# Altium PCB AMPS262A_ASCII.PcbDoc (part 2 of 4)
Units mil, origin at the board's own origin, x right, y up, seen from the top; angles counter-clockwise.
Board outline 5314.96 x 4803.15 mil, 4 copper layers (Top Layer, GND, Copper Layer 3, Bottom Layer), stack 79.28 mil thick; 324 components, 156 nets, 943 pads, 1411 vias.
Unrouted connection lines stored in the file: 130.
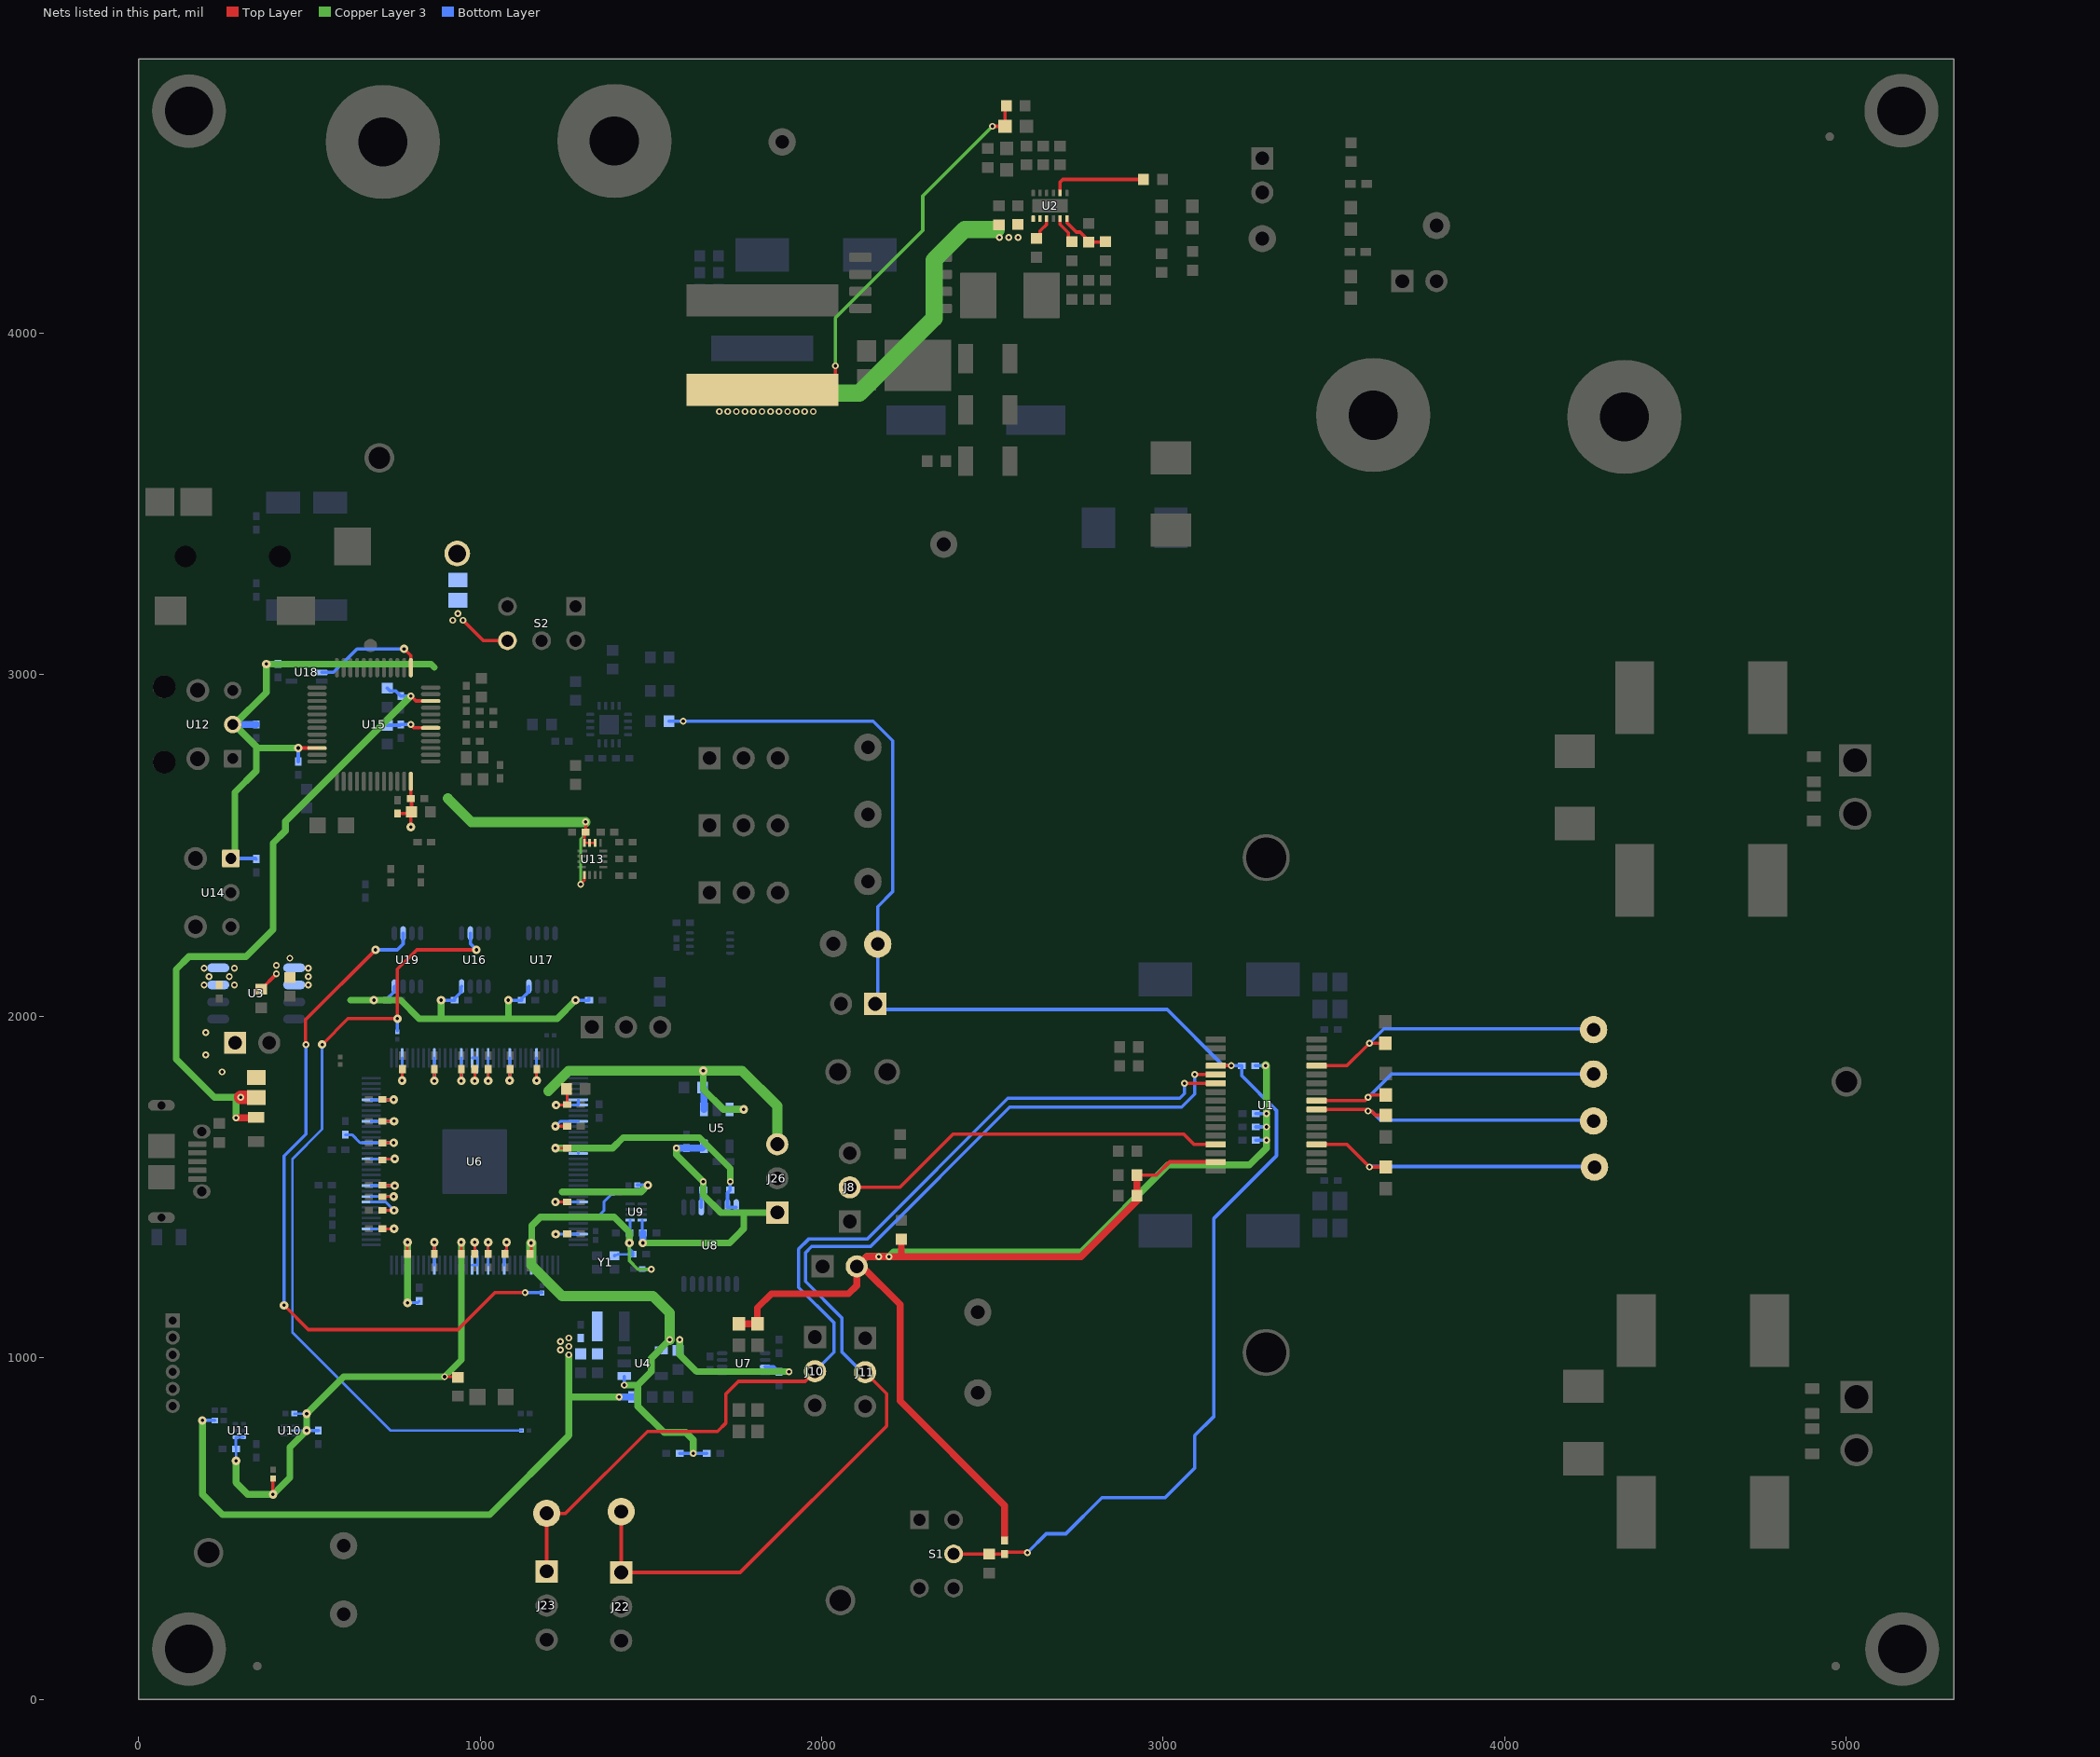
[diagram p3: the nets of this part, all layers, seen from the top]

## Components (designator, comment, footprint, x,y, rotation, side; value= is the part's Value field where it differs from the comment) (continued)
Y2 "ABM10-24.576MHZ-E20-T" XTAL_ABM10 984.25,2726.38 r180 top
ZZ1 "These assemblies are ESD sensitive, ESD precautions shall be observed." AssemblyNote 235,5703 r0 top
ZZ2 "These assemblies must be clean and free from flux and all contaminants. Use of no clean flux is not acceptable." AssemblyNote 235,5594.11 r0 top
ZZ3 "These assemblies must comply with workmanship standards IPC-A-610 Class 2, unless otherwise specified." AssemblyNote 235,5505.56 r0 top

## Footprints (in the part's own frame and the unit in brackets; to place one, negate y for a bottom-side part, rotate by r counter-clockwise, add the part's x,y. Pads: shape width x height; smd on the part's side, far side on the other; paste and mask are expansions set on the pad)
0201 [mm] "Data from Kemet datasheet CC101_COM dated 7/28/11"
  rect 0.46x0.42 smd mask+0: 1(-0.33,0) 2(0.33,0)
0201L [mm] "Data from Kemet datasheet CC101_COM dated 7/28/11"
  rect 0.36x0.32 smd mask+0: 1(-0.28,0) 2(0.28,0)
0402 [mm] "0402 from SM-752 data"
  rect 0.8x0.6 smd: 1(-0.6,0) 2(0.6,0)
  silkscreen extent -1.22,-0.52 1.22,0.52
0402L [mm] "0402 from SM-752 data"
  rect 0.6x0.5 smd: 1(-0.5,0) 2(0.5,0)
0603 [mm] "0603 from SM-752 data"
  rect 1x0.95 smd: 1(-0.8,0) 2(0.8,0)
  silkscreen extent -1.52,-0.69 1.52,0.69
0603L [mm] "0603 from SM-752 data"
  rect 0.8x0.85 smd: 1(-0.7,0) 2(0.7,0)
  silkscreen extent -0.07,-0.33 0.07,0.33
0805L [mm] "0805 from SM-752 data"
  rect 1.1x1.4 smd: 1(-0.75,0) 2(0.75,0)
1008 [mm] "SMD, Body 2.5x2mm, Height 1.2mm"
  rect 0.8x2.2 smd: 1(-1,0) 2(1,0)
  silkscreen extent -0.4,-1.2 0.4,1.2
1210_280 [mm] "SMD, 2-Leads, Body 3.6x2.8mm, Height 2.8mm"
  rect 1.1x2.2 smd: 1(-1.65,0) 2(1.65,0)
  silkscreen extent -0.84,-1.4 0.84,1.4
2512_WIDE_VISHAY [mm] "Vishay recommended land pattern"
  rect 1.9x7.6 smd: 1(-1.55,0) 2(1.55,0)
  silkscreen extent -0.3,-3.32 0.3,3.35
"APM_RM3X8MM 2701" [mm] "Screw, Dia 6.7mm, Length 8mm, TH"
  round 5.5 hole 3.6: ""(0,0)
  silkscreen extent -3.35,-3.35 3.35,3.35
AssemblyNote [mil] "Assembly Note"
CE_Mark_5mm [mil] "Minimum text height for CE Mark"
CONN_1040 [mil] "Test Point, PC  test point Terminal"
  round 75 hole 52: 1(0,0)
D0008A_M [mm] "SOIC, 8-Leads, Body 4.9x3.9mm, Pitch 1.27mm, IPC Low Density"
  oval 1.65x0.65 smd: 1(-2.825,1.905) 2(-2.825,0.635) 3(-2.825,-0.635) 4(-2.825,-1.905) 5(2.825,-1.905) 6(2.825,-0.635) 7(2.825,0.635) 8(2.825,1.905)
  silkscreen extent -3.3,-2.5 0.9,2.5
DAD0032A-MFG [mm] "Recommended Land Pattern"
  rrect22% 1.5x0.45 smd paste+0 mask+0: 1(-3.75,4.875) 2(-3.75,4.225) 3(-3.75,3.575) 4(-3.75,2.925) 5(-3.75,2.275) 6(-3.75,1.625) 7(-3.75,0.975) 8(-3.75,0.325) 9(-3.75,-0.325) 10(-3.75,-0.975) 11(-3.75,-1.625) 12(-3.75,-2.275) 13(-3.75,-2.925) 14(-3.75,-3.575) 15(-3.75,-4.225) 16(-3.75,-4.875) 17(3.75,-4.875) 18(3.75,-4.225) 19(3.75,-3.575) 20(3.75,-2.925) 21(3.75,-2.275) 22(3.75,-1.625) 23(3.75,-0.975) 24(3.75,-0.325) 25(3.75,0.325) 26(3.75,0.975) 27(3.75,1.625) 28(3.75,2.275) 29(3.75,2.925) 30(3.75,3.575) 31(3.75,4.225) 32(3.75,4.875)
  silkscreen extent -5.17,-5.55 3.1,5.55
DBV0005A_N [mm] "SOT23, 5-Leads, Body 2.9x1.6mm, Pitch 0.95mm, Lead Span 2.8mm, IPC Medium Density"
  rrect17% 1x0.6 smd: 1(-1.375,0.95) 2(-1.375,0) 3(-1.375,-0.95) 4(1.375,-0.95) 5(1.375,0.95)
  silkscreen extent -0.25,-1.55 0.25,1.55
DCK0005A_N [mm] "SOT353, 5-Leads, Body 2x1.3mm, Pitch 0.65mm, Lead Span 2.1mm, IPC Medium Density"
  rrect25% 0.85x0.4 smd: 1(-1.125,0.65) 2(-1.125,0) 3(-1.125,-0.65) 4(1.125,-0.65) 5(1.125,0.65)
  silkscreen extent -1.48,-1.02 0.55,1.1
DCT0008A_N [mm] "TSOP, 8-Leads, Body 3x2.8mm, Pitch 0.65mm, IPC Medium Density"
  oval 1.05x0.4 smd: 1(-1.975,0.975) 2(-1.975,0.325) 3(-1.975,-0.325) 4(-1.975,-0.975) 5(1.975,-0.975) 6(1.975,-0.325) 7(1.975,0.325) 8(1.975,0.975)
  silkscreen extent -2.32,-1.57 0.6,1.58
DCU0008A_L [mm] "TSSOP, 8-Leads, Body 2x2.3mm, Pitch 0.5mm, IPC High Density"
  oval 0.6x0.25 smd: 1(-1.5,0.75) 2(-1.5,0.25) 3(-1.5,-0.25) 4(-1.5,-0.75) 5(1.5,-0.75) 6(1.5,-0.25) 7(1.5,0.25) 8(1.5,0.75)
  silkscreen extent -1.05,-1.05 0.38,1.05
DCU0008A_N [mm] "TSSOP, 8-Leads, Body 2x2.3mm, Pitch 0.5mm, IPC Medium Density"
  oval 0.8x0.3 smd: 1(-1.6,0.75) 2(-1.6,0.25) 3(-1.6,-0.25) 4(-1.6,-0.75) 5(1.6,-0.75) 6(1.6,-0.25) 7(1.6,0.25) 8(1.6,0.75)
  silkscreen extent -1.05,-1.05 0.38,1.05
DQM0008A [mm] "TI"
  rrect50% 0.7x0.2 smd: 1(-0.45,0.6) 2(-0.45,0.2) 3(-0.45,-0.2) 4(-0.45,-0.6) 5(0.45,-0.6) 6(0.45,-0.2) 7(0.45,0.2) 8(0.45,0.6)
  silkscreen extent -0.72,-1.02 0.72,1.02
DRY0006A [mm] "USON-6"
  rrect67% 0.45x0.3 smd paste-0.05 mask+0: 1(-0.275,0.5)
  rrect67% 0.4x0.3 smd paste-0.05 mask+0: 2(-0.3,0) 3(-0.3,-0.5) 4(0.3,-0.5) 5(0.3,0) 6(0.3,0.5)
DSF0006A [mm] "TI recommended land pattern"
  rrect59% 0.6x0.17 smd mask+0: 1(-0.4,0.35) 2(-0.4,0) 3(-0.4,-0.35) 4(0.4,-0.35) 5(0.4,0) 6(0.4,0.35)
  silkscreen extent -0.6,-0.63 0.6,0.63
DSS0012B [mm] "WSON-10"
  rrect40% 0.5x0.25 smd: 1(-0.95,1.25) 2(-0.95,0.75) 3(-0.95,0.25) 4(-0.95,-0.25) 5(-0.95,-0.75) 6(-0.95,-1.25) 7(0.95,-1.25) 8(0.95,-0.75) 9(0.95,-0.25) 10(0.95,0.25) 11(0.95,0.75) 12(0.95,1.25)
  rrect11% 1x2.65 smd paste-0.5: 13(0,0)
ERJMS4S [mm] "SMD, 2-Leads, Body 6.4x3.2mm"
  rrect4% 2.7x3.4 smd: 1(-2.35,0) 2(2.35,0)
  silkscreen extent -0.7,-1.55 0.7,1.55
FCC_disclaimer_stacked [mil]
Fiducial6.4-20 [mil]
  round 25 smd mask+0: 1(0,0)
  Top Layer keep-out circle w46.37: c0,0 r19.68
FP-ASA-24.000MHZ-L-T_SMD_2MM0_1MM6-MFG [mm]
  rrect15% 0.75x0.65 smd paste+0 mask+0: 1(-0.65,-0.5) 2(0.65,-0.5) 3(0.65,0.5) 4(-0.65,0.5)
  silkscreen extent -1.45,-1.52 1.45,0.85
FP-CGA4J3X7R1H684M125AB_0805-MFG [mm]
  rrect13% 0.8x1.05 smd paste+0 mask+0: 1(-0.925,0) 2(0.925,0)
FP-FCR684208T_OTJ8-MFG [mm]
  rrect8% 1.3x1.3 hole 0.8 paste-1000 mask+0: 1(-4.25,2.54)
  round 1.3 hole 0.8 paste-1000 mask+0: 2(-4.25,0) 3(-4.25,-2.54)
  round 1.7 hole 1.1 paste-1000 mask+0: 4(-1.65,2.54) 5(-1.65,-2.54)
  round 1.7 hole 1.7 unplated paste-1000 mask+0: ""(0.85,2.8) ""(0.85,-2.8)
  silkscreen extent -7.45,-4.95 6.85,4.95
FP-PLR237/T10BK_PTH_9MM70_13MM50-MFG [mm] "EVERLIGHT"
  rrect8% 1.3x1.3 hole 0.8 paste-1000 mask+0: 1(-2.54,4.36)
  round 1.3 hole 0.8 paste-1000 mask+0: 2(0,4.36) 3(2.54,4.36)
  round 1.7 hole 1.1 paste-1000 mask+0: 4(-2.54,1.74) 5(2.54,1.74)
  silkscreen extent -5.6,-6.9 5,6.9
HARWIN_S1911-46R [mm] "HARWIN"
  rect 2.48x3 smd mask+0: 1(-2.69,0) 2(2.69,0)
  silkscreen extent -0.5,-1.5 0.5,1.5
HSINK_ATS078036036-TI1OP-519-C1-R3 [mm] "TH, 2-Leads, Body 78x36mm, Height 35.6mm"
  round 3.5 hole 3: 1(-18.4,0) 2(18.4,0)
HXB_JA0 [mm] "SMD, 2-Leads, Dia 10mm"
  rect 4.4x2.2 smd: 1(-4.45,0) 2(4.45,0)
  silkscreen extent -5.25,-5.25 5.25,5.25
JST_B2PS-VH [mm] "JST Sales America Inc"
  rect 2.4x2.4 hole 1.778: 1(0,1.98)
  round 2.4 hole 1.778: 2(0,-1.98)
  silkscreen extent 2,-3.93 14.9,3.93
Keystone5003 [mil] "For Keystone 500x miniature loop terminals"
  round 80 hole 40: 1(0,0)
  silkscreen extent -52,-52 52,52
Keystone5006 [mil] "Keystone Compact loops"
  round 87 hole 63: 1(0,0)
  silkscreen extent -70,-70 70,70
Keystone_7006 [mm] "KEYSTONE"
  round 8.5 hole 3.658: 1(0,0)
  silkscreen extent -4.8,-4.8 4.8,4.8
Keystone_7007 [mm] "KEYSTONE"
  round 8.5 hole 3.658: 1(0,0)
  silkscreen extent -4.8,-4.8 4.8,4.8
Keystone_24434 [mil] "Keystone"
LTST-C170TBKT_Blue [mm] "LITE-ON"
  rect 1.2x1.2 smd: 1(-1.05,0) 2(1.05,0)
  silkscreen extent -1.6,-1 2.2,1
Molex_0475890001 [mm] "Molex"
  rrect25% 0.4x1.35 smd: 1(-1.3,4.125) 2(-0.65,4.125) 3(0,4.125) 4(0.65,4.125) 5(1.3,4.125)
  oval 1.05x1.3 hole 0.7 slot 0.85 at 90 deg: 6(2.225,4.45) 11(-2.225,4.45)
  oval 0.8x2 hole 0.6 slot 1.3 at 90 deg: 7(4.175,1.45) 10(-4.175,1.45)
  rrect6% 1.8x2 smd: 8(1.15,1.45) 9(-1.15,1.45)
  silkscreen extent -3.75,2.85 3.75,4.3
MPZ2012 [mm] "TDK"
  rect 0.8x1.2 smd: 1(-0.9,0) 2(0.9,0)
PBC03SAAN [mm] "Sullins 100mil, 1x3, 230 mil above insulator"
  rect 1.65x1.65 hole 1.016: 1(-2.54,0)
  round 1.65 hole 1.016: 2(0,0) 3(2.54,0)
  silkscreen extent -3.81,-1.27 3.81,1.27
PG-TDSON-8-33 [mm] "Infineon recommended land pattern"
  rrect29% 1.65x0.7 smd paste-1 mask+0: 1(-2.995,1.905) 2(-2.995,0.635) 3(-2.995,-0.635) 4(-2.995,-1.905) 5(2.995,-1.905) 6(2.995,-0.635) 7(2.995,0.635) 8(2.995,1.905)
PT0048A_N [mm] "Thin QFP, 48-Leads, Body 7x7mm, Pitch 0.5mm, IPC Medium Density"
  oval 1.45x0.3 smd: 1(-4.225,2.75) 2(-4.225,2.25) 3(-4.225,1.75) 4(-4.225,1.25) 5(-4.225,0.75) 6(-4.225,0.25) 7(-4.225,-0.25) 8(-4.225,-0.75) 9(-4.225,-1.25) 10(-4.225,-1.75) 11(-4.225,-2.25) 12(-4.225,-2.75) 25(4.225,-2.75) 26(4.225,-2.25) 27(4.225,-1.75) 28(4.225,-1.25) 29(4.225,-0.75) 30(4.225,-0.25) 31(4.225,0.25) 32(4.225,0.75) 33(4.225,1.25) 34(4.225,1.75) 35(4.225,2.25) 36(4.225,2.75)
  oval 0.3x1.45 smd: 13(-2.75,-4.225) 14(-2.25,-4.225) 15(-1.75,-4.225) 16(-1.25,-4.225) 17(-0.75,-4.225) 18(-0.25,-4.225) 19(0.25,-4.225) 20(0.75,-4.225) 21(1.25,-4.225) 22(1.75,-4.225) 23(2.25,-4.225) 24(2.75,-4.225) 37(2.75,4.225) 38(2.25,4.225) 39(1.75,4.225) 40(1.25,4.225) 41(0.75,4.225) 42(0.25,4.225) 43(-0.25,4.225) 44(-0.75,4.225) 45(-1.25,4.225) 46(-1.75,4.225) 47(-2.25,4.225) 48(-2.75,4.225)
  silkscreen extent -4.35,-3.1 3.1,3.58
PW0014A_L [mm] "TSOP, 14-Leads, Body 5x4.4mm, Pitch 0.65mm, IPC High Density"
  oval 1.2x0.4 smd: 1(-2.85,1.95) 2(-2.85,1.3) 3(-2.85,0.65) 4(-2.85,0) 5(-2.85,-0.65) 6(-2.85,-1.3) 7(-2.85,-1.95) 8(2.85,-1.95) 9(2.85,-1.3) 10(2.85,-0.65) 11(2.85,0) 12(2.85,0.65) 13(2.85,1.3) 14(2.85,1.95)
  silkscreen extent -3.2,-2.55 1.85,2.55
RGT0016A [mm] "QFN, 16-Leads, Body 3x3mm, Pitch 0.5mm, Thermal Pad 1.45x1.45mm, TI Recommended"
  rrect42% 0.6x0.24 smd: 1(-1.4,0.75) 2(-1.4,0.25) 3(-1.4,-0.25) 4(-1.4,-0.75) 9(1.4,-0.75) 10(1.4,-0.25) 11(1.4,0.25) 12(1.4,0.75)
  rrect42% 0.24x0.6 smd: 5(-0.75,-1.4) 6(-0.25,-1.4) 7(0.25,-1.4) 8(0.75,-1.4) 13(0.75,1.4) 14(0.25,1.4) 15(-0.25,1.4) 16(-0.75,1.4)
  rrect7% 1.34x1.34 on Bottom Paste: 17(0,0)
  rrect7% 1.45x1.45 smd paste-0.725: 17(0,0)
  silkscreen extent -1.72,-1.73 1.72,1.73
RSV0016A [mm] "QFN, 16-Leads, Body 1.8x2.6mm, Pitch 0.4mm, TI Recommended"
  rect 0.7x0.2 smd: 1(-0.75,0.6)
  rect 0.6x0.2 smd: 2(-0.8,0.2) 3(-0.8,-0.2) 4(-0.8,-0.6) 9(0.8,-0.6) 10(0.8,-0.2) 11(0.8,0.2) 12(0.8,0.6)
  rect 0.2x0.6 smd: 5(-0.6,-1.2) 6(-0.2,-1.2) 7(0.2,-1.2) 8(0.6,-1.2) 13(0.6,1.2) 14(0.2,1.2) 15(-0.2,1.2) 16(-0.6,1.2)
  silkscreen extent -1.08,-1.33 1.08,1.45
SM_RADIAL_10BMM [mm] "Nichicon 10x10"
  rect 4x2.5 smd: 1(-4,0) 2(4,0)
  silkscreen extent -5.25,-5.25 5.25,5.25
SM_RADIAL_B [mm] "4 x 5.8mm:  Panasonic B"
  rect 2.5x1.6 smd: 1(-1.75,0) 2(1.75,0)
  silkscreen extent -2.24,-2.25 2.25,2.25
SNT-100-BK-G [mil] "Samtec STEP model"
  round 1 on Mech3: 0(0,0)
SOT1289 [mm] "CFP15, Nexperia recommended land pattern"
  rect 1.6x1.44 smd paste-0.8 mask+0: 1(-1.065,2.78) 2(1.065,2.78)
  rect 3.8x4.96 smd paste-2.48 mask+0: 3(0,-1.02)
SULLINS_LPPB061NGCN-RC [mm] "SULLINS"
  rect 1.05x1.05 hole 0.61: 1(3.175,2.54)
  round 1.05 hole 0.61: 2(1.905,2.54) 3(0.635,2.54) 4(-0.635,2.54) 5(-1.905,2.54) 6(-3.175,2.54)
  silkscreen extent -4,-2.37 4.03,2
Sullins_PBC02SAAN [mm] "Sullins 100mil, 1x2, 230 mil above insulator"
  rect 1.65x1.65 hole 1.016: 1(0,1.27)
  round 1.65 hole 1.016: 2(0,-1.27)
  silkscreen extent -1.37,-2.54 1.27,3.1
SW_200USP1T1A1M2 [mm] "TH, 5-Leads, Body 7x4.5mm, Pitch 2.54mm"
  rect 1.4x1.4 hole 0.9: 1(-1.27,2.54)
  round 1.4 hole 0.9: 3(-1.27,-2.54) 4(1.27,2.54) 5(1.27,0) 6(1.27,-2.54)
  silkscreen extent -2.7,-3.63 2.38,3.63
Switchcraft_35RASM [mil] "Switchcraft"
  rect 83x92 smd: 1(-159.5,142.5) 2(159.5,67.5)
  rect 83x111 smd: 3(-159.5,-224.5)
  rect 83x84 smd: 4(159.5,173.5)
  rect 111x107 smd: 5(29,-390.5)
  rect 0x0 hole 63 unplated: MH1(0,98.5) MH2(0,-177.5)
  silkscreen extent -161,-339 121,340
TI_Stacked_Overlay_Small [mil]
TP_SM_1MM [mm] "1mm Test Point, SMT"
  round 1 smd paste-0.5: 1(0,0)
TQFP-128 [mm] "TQFP, 128-Leads, Body 14x14mm, Pitch 0.4mm"
  rrect50% 1.45x0.2 smd: 1(-7.7,6.2) 2(-7.7,5.8) 3(-7.7,5.4) 4(-7.7,5) 5(-7.7,4.6) 6(-7.7,4.2) 7(-7.7,3.8) 8(-7.7,3.4) 9(-7.7,3) 10(-7.7,2.6) 11(-7.7,2.2) 12(-7.7,1.8) 13(-7.7,1.4) 14(-7.7,1) 15(-7.7,0.6) 16(-7.7,0.2) 17(-7.7,-0.2) 18(-7.7,-0.6) 19(-7.7,-1) 20(-7.7,-1.4) 21(-7.7,-1.8) 22(-7.7,-2.2) 23(-7.7,-2.6) 24(-7.7,-3) 25(-7.7,-3.4) 26(-7.7,-3.8) 27(-7.7,-4.2) 28(-7.7,-4.6) 29(-7.7,-5) 30(-7.7,-5.4) 31(-7.7,-5.8) 32(-7.7,-6.2) 65(7.7,-6.2) 66(7.7,-5.8) 67(7.7,-5.4) 68(7.7,-5) 69(7.7,-4.6) 70(7.7,-4.2) 71(7.7,-3.8) 72(7.7,-3.4) 73(7.7,-3) 74(7.7,-2.6) 75(7.7,-2.2) 76(7.7,-1.8) 77(7.7,-1.4) 78(7.7,-1) 79(7.7,-0.6) 80(7.7,-0.2) 81(7.7,0.2) 82(7.7,0.6) 83(7.7,1) 84(7.7,1.4) 85(7.7,1.8) 86(7.7,2.2) 87(7.7,2.6) 88(7.7,3) 89(7.7,3.4) 90(7.7,3.8) 91(7.7,4.2) 92(7.7,4.6) 93(7.7,5) 94(7.7,5.4) 95(7.7,5.8) 96(7.7,6.2)
  rrect50% 0.2x1.45 smd: 33(-6.2,-7.7) 34(-5.8,-7.7) 35(-5.4,-7.7) 36(-5,-7.7) 37(-4.6,-7.7) 38(-4.2,-7.7) 39(-3.8,-7.7) 40(-3.4,-7.7) 41(-3,-7.7) 42(-2.6,-7.7) 43(-2.2,-7.7) 44(-1.8,-7.7) 45(-1.4,-7.7) 46(-1,-7.7) 47(-0.6,-7.7) 48(-0.2,-7.7) 49(0.2,-7.7) 50(0.6,-7.7) 51(1,-7.7) 52(1.4,-7.7) 53(1.8,-7.7) 54(2.2,-7.7) 55(2.6,-7.7) 56(3,-7.7) 57(3.4,-7.7) 58(3.8,-7.7) 59(4.2,-7.7) 60(4.6,-7.7) 61(5,-7.7) 62(5.4,-7.7) 63(5.8,-7.7) 64(6.2,-7.7) 97(6.2,7.7) 98(5.8,7.7) 99(5.4,7.7) 100(5,7.7) 101(4.6,7.7) 102(4.2,7.7) 103(3.8,7.7) 104(3.4,7.7) 105(3,7.7) 106(2.6,7.7) 107(2.2,7.7) 108(1.8,7.7) 109(1.4,7.7) 110(1,7.7) 111(0.6,7.7) 112(0.2,7.7) 113(-0.2,7.7) 114(-0.6,7.7) 115(-1,7.7) 116(-1.4,7.7) 117(-1.8,7.7) 118(-2.2,7.7) 119(-2.6,7.7) 120(-3,7.7) 121(-3.4,7.7) 122(-3.8,7.7) 123(-4.2,7.7) 124(-4.6,7.7) 125(-5,7.7) 126(-5.4,7.7) 127(-5.8,7.7) 128(-6.2,7.7)
  rrect2% 4.8x4.8 smd paste-4.8: 129(0,0)
  silkscreen extent -7.1,-7.1 7.1,7.1
WE-PD_1210 [mm] "Wurth Elektronik recommended land pattern"
  rect 2.9x5.4 smd: 1(-4.95,0) 2(4.95,0)
  silkscreen extent -6,-6 6,6
WEEE_Minimum [mil] "WEEElie bin"
  silkscreen extent 22,-71 54,74
XAL1010 [mm] "COILCRAFT"
  rect 2.38x11.31 smd: 1(-3.325,0) 2(3.325,0)
  silkscreen extent -5.3,-6 5.3,6
XTAL_ABM10 [mm] "ABRACON"
  rect 0.8x0.9 smd: 1(-0.625,0.825) 2(-0.625,-0.825) 3(0.625,-0.825) 4(0.625,0.825)
  silkscreen extent -1.28,-0.13 1.05,1.52

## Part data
C1 C10 C13 C21: library part CMP-0086459-1, "CAP CER 0.68UF 50V X7R 0805"
C2 C3 C6 C7: library part CMP-0007842-2, "CAP, CERM, 10 uF, 35 V, +/- 10%, X5R, 0805"
C4 C5: library part CMP-0006325-2, "CAP, CERM, 0.1 uF, 50 V, +/- 10%, X7R, AEC-Q200 Grade 1, 0402"
C8 C9: library part CMP-0011092-1, "CAP, AL, 390 uF, 35 V, +/- 20%, 0.08 ohm, SMD"
C11: library part CMP-0006949-5, "CAP, CERM, 4.7 uF, 10 V, +/- 10%, X5R, 0603"
C12 C22: library part CMP-0006860-5, "CAP, CERM, 0.1 uF, 16 V, +/- 10%, X7R, 0603"
C14 C16 C18 C20: library part CMP-0007050-4, "CAP, CERM, 0.47 uF, 50 V, +/- 10%, X7R, 0603"
C15 C17 C19: library part CMP-0082012-1, "CAP, CERM, 1 µF, 16 V,+/- 20%, X7R, 0603"
C23: library part CMP-0012596-3, "CAP, Polymer Hybrid, 100 uF, 50 V, +/- 20%, 28 ohm, 10x10 SMD"
C24 C25 C26: library part CMP-0860569-1, "CAP, CERM, 10 µF, 25 V,+/- 10%, X5R, 0603"
C27: library part CMP-0080610-1, "CAP, CERM, 0.1 µF, 25 V,+/- 10%, X7R, AEC-Q200 Grade 1, 0402"
C28: library part CMP-0007078-4, "CAP, CERM, 0.1 uF, 50 V, +/- 10%, X7R, AEC-Q200 Grade 1, 0603"
C29 C30 C31: library part CMP-0009162-2, "CAP, CERM, 4.7 uF, 50 V, +/- 10%, X7R, AEC-Q200 Grade 1, 1210"
C32: library part CMP-0012269-3, "CAP, Aluminum Polymer, 100 uF, 50 V, +/- 20%, 0.025 ohm, AEC-Q200 Grade 2, D10xL10mm SMD"
C33: library part CMP-0007137-5, "CAP, CERM, 1 uF, 16 V, +/- 20%, X7R, AEC-Q200 Grade 1, 0603"
C34: library part CMP-0007143-4, "CAP, CERM, 0.01 uF, 50 V, +/- 10%, X7R, AEC-Q200 Grade 1, 0603"
C35 C36: library part CMP-0080091-1, "CAP, CERM, 100 pF, 50 V,+/- 1%, C0G/NP0, 0603"
C37: library part CMP-0007094-5, "CAP, CERM, 0.22 uF, 50 V, +/- 10%, X7R, AEC-Q200 Grade 1, 0603"
C38: library part CMP-0007072-4, "CAP, CERM, 220 pF, 20 V, +/- 5%, C0G/NP0, AEC-Q200 Grade 1, 0603"
C39: library part CMP-0006900-4, "CAP, CERM, 0.022 uF, 16 V, +/- 10%, X7R, 0603"
C40 C41: library part CMP-0079606-1, "CAP, CERM, 220 pF, 50 V,+/- 5%, C0G/NP0, AEC-Q200 Grade 1, 0402"
C42 C44 C45 C46 C47 C48 C49 C50 C51 C52 C53 C54 C55 C56 C57 C61 C65 C66 C67 C68 C69 C70 C71 C72 C73 C74 C75 C76 C77 C78 C79 C80 C81 C82 C83 C85 C86 C88 C89 C90 C91 C92 C93 C94 C95 C97 C99 C100 C104 C111 C114 C115 C116 C117 C118 C119 C120: library part CMP-0006228-2, "CAP, CERM, 0.1 uF, 16 V, +/- 10%, X7R, 0402"
C43 C62: library part CMP-0007003-5, "CAP, CERM, 10 uF, 10 V, +/- 20%, X5R, 0603"
C58 C59 C60: library part CMP-0007005-5, "CAP, CERM, 22 uF, 10 V, +/- 20%, X5R, 0603"
C63: library part CMP-0006372-2, "CAP, CERM, 1 uF, 6.3 V, +/- 20%, X5R, 0402"
C64: library part CMP-0006227-2, "CAP, CERM, 0.01 uF, 16 V, +/- 10%, X7R, 0402"
C84: library part CMP-0006470-2, "CAP, CERM, 470 pF, 50 V, +/- 5%, C0G/NP0, 0402"
C87: library part CMP-0007370-4, "CAP, CERM, 2.2 uF, 10 V, +/- 10%, X7R, 0603"
C96 C98 C101 C110: library part CMP-0007122-5, "CAP, CERM, 10 uF, 16 V, +/- 20%, X5R, 0603"
C102 C103 C107: library part CMP-0006215-2, "CAP, CERM, 10 pF, 50 V, +/- 5%, C0G/NP0, 0402"
C105 C106: library part CMP-0006365-2, "CAP, CERM, 27 pF, 50 V, +/- 5%, C0G/NP0, 0402"
C108 C109: library part CMP-0010644-1, "CAP, AL, 10 uF, 16 V, +/- 20%, 3 ohm, SMD"
C112: library part CMP-0860557-1, "CAP, CERM, 4700 pF, 25 V,+/- 10%, X7R, 0402"
C113: library part CMP-0006331-2, "CAP, CERM, 0.068 uF, 50 V, +/- 10%, X7R, AEC-Q200 Grade 1, 0402"
D1: library part CMP-0028984-3, "Diode, Schottky, 60 V, 10 A, AEC-Q101, CFP15"
D2 D3: library part CMP-0002889-2, "LED, Blue, SMD"
FID1 FID2 FID3 FID4 FID5 FID6: library part CMP-0077181-1, "Fiducial mark.  There is nothing to buy or mount."
H1: library part CMP-0004031-2, "Heat Sink, Vertical"
H2 H3 H4 H5: library part CMP-0003717-1, "MACHINE SCREW PAN PHILLIPS M3"
H6 H7 H8 H9: library part CMP-0003665-1, "Standoff, Hex, 12mm, M3, Aluminum"
J1 J7 J14 J18: library part CMP-0075020-1, "JUMPER TIN SMD"
J2 J6: library part CMP-0074989-1, "Header (friction lock), 3.96mm, 2x1, Tin, R/A, TH"
J3 J9 J15 J16 J19: library part CMP-0054566-1, "Header, 100mil, 2x1, Gold, TH"
J4 J5 J21: library part CMP-0055161-1
J8 J10 J11 J22 J23 J26 J27 J28 J29 J31: library part CMP-0002334-1, "Header, 100mil, 3x1, Gold, TH"
J12 J17: library part CMP-0055127-1, "Binding Post, RED, TH"
J13 J20: library part CMP-0055128-1, "Binding Post, BLACK, TH"
J24: library part CMP-0054640-1, "Receptacle, 50mil, 6x1, Gold, R/A, TH"
J25: library part CMP-0055301-1, "Connector, Receptacle, Micro-USB Type AB, R/A, Bottom Mount SMT"
J30: library part CMP-0074987-1, "Audio Jack, 3.5mm, Stereo, R/A, SMT"
L1 L2 L3 L4: library part CMP-0064206-1, "Inductor, Shielded Drum Core, Ferrite, 10 uH, 7.1 A, 0.01294 ohm, SMD"
L5: library part CMP-0060953-1, "Inductor, Shielded, Composite, 6.8 uH, 18.5 A, 0.01 ohm, SMD"
L6: library part CMP-0058752-1, "Inductor, Multilayer, Ferrite, 2.2 uH, 1.3 A, 0.08 ohm, SMD"
L7 L8: library part CMP-0003429-3, "Ferrite Bead, 600 ohm @ 100 MHz, 2 A, 0805"
Logo1: library part CMP-0074844-2
Logo2: library part CMP-0074838-1, "Texas Instrument Corporate Signature"
Logo3: library part CMP-0074847-1, "FCC_disclaimer"
Logo4: library part CMP-0074769-4
Q1: library part CMP-0080659-3, "MOSFET, N-CH, 40 V, 50 A, AEC-Q101, SON-8"
R1 R6 R15 R17 R22 R25 R26 R30 R73 R74 R75 R76 R77 R78 R80: library part CMP-0025885-5, "RES, 0, 5%, 0.1 W, 0603"
R2: library part CMP-0065359-1, "RES, 15.0 k, .1%, .063 W, AEC-Q200 Grade 0, 0402"
R3 R36: library part CMP-0026852-3, "RES, 1.0 k, 5%, 0.063 W, AEC-Q200 Grade 0, 0402"
R4 R5 R7 R66 R79: library part CMP-0025958-3, "RES, 10.0 k, 1%, 0.063 W, AEC-Q200 Grade 0, 0402"
R8 R9: library part CMP-0025906-5, "RES, 2.2 k, 5%, 0.1 W, 0603"
R10 R11: library part CMP-0025899-5, "RES, 1.0 k, 5%, 0.1 W, 0603"
R12: library part CMP-0015368-2, "RES, 0, 5%, 2 W, 2512 WIDE"
R13 R19: library part CMP-0022914-5, "RES, 21.0 k, 1%, 0.1 W, 0603"
R14 R64: library part CMP-0023343-3, "RES, 0, 1%, 0.1 W, AEC-Q200 Grade 0, 0603"
R16: library part CMP-0022944-5, "RES, 24.9 k, 1%, 0.1 W, 0603"
R18: library part CMP-0022736-4, "RES, 100, 1%, 0.1 W, 0603"
R20: library part CMP-0022447-4, "RES, 49.9 k, 1%, 0.1 W, AEC-Q200 Grade 0, 0603"
R21: library part CMP-0015077-2, "RES, 0.004, 1%, 3 W, AEC-Q200 Grade 0, 6.4x3.2mm"
R23: library part CMP-0023239-5, "RES, 68.0 k, 1%, 0.1 W, 0603"
R24: library part CMP-0022017-4, "RES, 11.3 k, 1%, 0.1 W, AEC-Q200 Grade 0, 0603"
R27 R28: library part CMP-0022684-3, "RES, 10.0 k, 1%, 0.1 W, 0603"
R29: library part CMP-0023148-5, "RES, 4.30 k, 1%, 0.1 W, 0603"
R31 R33: library part CMP-0020803-2, "RES, 0, 5%, 0.125 W, 0805"
R32: library part CMP-0022941-4, "RES, 249 k, 1%, 0.1 W, 0603"
R34: library part CMP-0023232-5, "RES, 66.5 k, 1%, 0.1 W, 0603"
R35: library part CMP-0022735-5, "RES, 100 k, 1%, 0.1 W, 0603"
R37 R38: library part CMP-0026890-5, "RES, 2.2 k, 5%, 0.063 W, AEC-Q200 Grade 0, 0402"
R39 R46: library part CMP-0026658-1, "RES, 10.0 k, 1%, 0.1 W, 0402"
R40: library part CMP-0025821-4, "RES, 4.7, 5%, 0.1 W, AEC-Q200 Grade 0, 0603"
R41: library part CMP-0026825-5, "RES, 10 k, 5%, 0.063 W, AEC-Q200 Grade 0, 0402"
R42 R43 R44 R47 R52 R53 R56: library part CMP-0027614-1, "RES, 33.2, 1%, 0.05 W, 0201"
R45: library part CMP-0023235-5, "RES, 680, 1%, 0.1 W, 0603"
R48: library part CMP-0065361-1, "RES, 0, 5%, .05 W, AEC-Q200 Grade 0, 0201"
R49: library part CMP-0082538-1, "RES, 43.2, 1%, 0.1 W, AEC-Q200 Grade 0, 0402"
R50 R51 R55 R57 R72: library part CMP-0027262-3, "RES, 10.0 k, 1%, 0.05 W, 0201"
R54: library part CMP-0027523-1, "RES, 25.5 k, 1%, 0.05 W, 0201"
R58: library part CMP-0027757-1, "RES, 51.0 k, 1%, 0.05 W, 0201"
R59: library part CMP-0026737-1, "RES, 47.0 k, 1%, 0.0625 W, 0402"
R60 R65 R67: library part CMP-0026404-2, "RES, 49.9, 1%, 0.063 W, AEC-Q200 Grade 0, 0402"
R61 R62 R63: library part CMP-0026696-1, "RES, 33.0, 1%, 0.1 W, 0402"
R68: library part CMP-0025733-4, "RES, 1.5 k, 5%, 0.1 W, AEC-Q200 Grade 0, 0603"
R69 R70: library part CMP-0026873-2, "RES, 200 k, 5%, 0.063 W, AEC-Q200 Grade 0, 0402"
R71: library part CMP-0026962-3, "RES, 680, 5%, 0.063 W, AEC-Q200 Grade 0, 0402"
S1 S2: library part CMP-0002209-2, "Switch, SPDT, On-On, 2 Pos, TH"
SH-J1 SH-J2 SH-J3 SH-J4 SH-J5 SH-J6 SH-J7 SH-J8 SH-J9 SH-J10: library part CMP-0003623-3, "Shunt, 100mil, Gold plated, Black"
TP1 TP2 TP3 TP4 TP5 TP6 TP7 TP8 TP13 TP14 TP16 TP17 TP18 TP19 TP20 TP21 TP22 TP23 TP24: library part CMP-0055140-2, "Test Point, Miniature, Orange, TH"
TP9 TP10 TP11 TP12: library part CMP-0055143-2, "Test Point, Compact, Black, TH"
TP15: library part CMP-0003825-1, "1mm Test Point, SMT"
U1: library part CMP-0124450-1
U2: library part CMP-0085413-1, "2.2-MHz Wide Input Nonsynchronous Boost, Sepic, Flyback Controller, DSS0012B (WSON-12)"
U3: library part CMP-0036485-1, "Single Output Fast Transient Response LDO, 1 A, Fixed 3.3 V Output, 2.7 to 10 V Input, with Low IQ, 8-pin SOIC (D), -40 to 125 degC, Green (RoHS & no Sb/Br)"
U4: library part CMP-0013046-2, "1-A High Efficiency Step-Down Converter in SOT23-5 Package, DBV005A, DBV0005A (SOT-5)"
U5: library part CMP-0036854-2, "Single Output LDO, 400mA, Adj.(1.2 to 5.5V), Cap free, Low Noise, Reverse Current Protection, DBV0005A (SOT-23-5)"
U6: library part CMP-0092035-2, "XCore XEF Microcontroller IC 32-Bit 16-Core 2000MIPs 2MB (2M x 8) FLASH 128-TQFP (14x14)"
U7: library part CMP-0043323-2, "2-Bit Bidirectional 1-MHz I2C Bus and SMBus Voltage-Level Shifter, DCU0008A (VSSOP-8)"
U8: library part CMP-0065668-3, "Programmable 1-PLL VCXO Clock Synthesizer with 2.5-V or 3.3-V LVCMOS Outputs, PW0014A (TSSOP-14)"
U9: library part CMP-0050936-4, "Dual-Bit Dual-Supply Bus Transceiver, DQM0008A (X2SON-8)"
U10: library part CMP-0051795-5, "Enhanced Product Dual Buffer/Driver with Open-Drain Output, DCK0006A (SOT-SC70-6)"
U11: library part CMP-0032427-3, "Single-Channel Ultra-Small Adjustable Supervisory Circuit With Active-High Open-Drain Output, DRY0006A (USON-6)"
U12: library part CMP-0098162-1, "Optical Jack Transmitter OTJ-8"
U13: library part CMP-0066452-2, "4-Bit Dual-Supply Bus Transceiver With Configurable Voltage-Level Shifting and 3-State Outputs, RSV0016A (UQFN-16)"
U14: library part CMP-0097438-1, "Optical Receiver 25Mbps Single 650nm"
U15: library part CMP-0028694-1, "216 kHz Digital Audio Interface Transceiver (DIX) with Stereo ADC and Routing, PCM, S / PDIF, ADC, 4.5 - 5.5V for Analog, 2.9 - 3.6V for DIX, -40 to 85 degC, 48-Pin LQFP (PT), Green (RoHS & no Sb/Br)"
U16 U17 U19: library part CMP-0051024-2, "Single 2-Line to 1-Line Data Selector/Multiplexer, DCT0008A, LARGE T&R"
U18: library part CMP-0051641-4, "Single Schmitt-Trigger Inverter, DCK0005A (SOT-SC70-5)"
U20: library part CMP-0051026-2, "Single 2-Line to 1-Line Data Selector/Multiplexer, DCU0008A, LARGE T&R"
U21: library part CMP-0043157-2, "Low-Voltage 8-Bit I2C and SMBus I/O Expander, 1.65 to 5.5 V, -40 to 85 degC, 16-pin QFN (RGT), Green (RoHS & no Sb/Br)"
Y1: library part CMP-0096068-1, "Crystal Oscillator 24MHz ±50ppm HCMOS 3.3V SMD 2x1.6mm"
Y2: library part CMP-0004590-3, "Crystal, 24.576 MHz, 10pF, SMD"
ZZ1: library part CMP-0077236-1
ZZ2: library part CMP-0077237-1
ZZ3: library part CMP-0077238-1

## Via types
v1: diameter 20, hole 10, Top Layer to Bottom Layer, tented both sides, 1299 vias
v2: diameter 25, hole 10, Top Layer to Bottom Layer, tented both sides, 87 vias
v3: diameter 23.62, hole 11.81, Top Layer to Bottom Layer, 12 vias
v4: diameter 19.68, hole 7.87, Top Layer to Bottom Layer, 7 vias
v5: diameter 20, hole 10, Top Layer to Bottom Layer, 6 vias

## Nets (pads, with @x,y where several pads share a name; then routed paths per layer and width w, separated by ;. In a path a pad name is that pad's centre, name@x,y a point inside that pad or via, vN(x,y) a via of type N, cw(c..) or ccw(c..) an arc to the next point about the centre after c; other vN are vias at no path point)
1.0V: C59.1 C60.1 C61.1 C65.2 C66.2 C67.2 C68.2 C69.2 C70.2 C71.2 C72.2 C73.2 C74.2 C75.2 C76.2 C77.2 C78.2 L6.2 R34.2 R40.1 R54.1 U6.11 U6.16 U6.17 U6.24 U6.36 U6.41 U6.49 U6.56 U6.60 U6.73 U6.80 U6.81 U6.87 U6.101 U6.102 U6.120 U6.126 | length 3405.1
  Top Layer w7.87: C68.2@713.58,1377.95 v2(748.03,1377.95) ; C69.2@713.58,1432.09 v2(748.03,1432.09) ; C70.2@713.58,1579.72 716.54,1582.68 v2(750,1582.68) ; C71.2@713.58,1692.91 v2(748.03,1692.91) ; C72.2@713.58,1756.89 714.57,1755.91 v2(747.05,1755.91) v2@748.03,1754.92 ; C67.2@866.14,1304.13 v2(866.14,1338.58) ; v2(866.14,1811.02) C73.2@866.14,1845.47 ; C66.2@984.25,1304.13 v2(984.25,1338.58) ; v2(984.25,1811.02) C74.2@984.25,1845.47 ; C65.2@1072.83,1304.13 1077.76,1309.06 v2(1077.76,1338.58) ; v2(1086.61,1812.01) 1086.61,1844.49 C75.2@1087.6,1845.47 ; v2@1220.47,1361.22 v2(1221.46,1362.2) v2@1222.44,1363.19 ; v2(1220.47,1456.69) C77.2@1254.92,1456.69 ; v2(1222.44,1740.16) 1252.95,1740.16 C76.2@1254.92,1742.13 1254.92,1778.54 R40.1@1251.97,1781.5 ; C78.2@1253.94,1362.2 C78.2@1254.92,1363.19
  Copper Layer 3 w19.68: v2(187.01,816.93) 187.01,600.39 246.06,541.34 1028.54,541.34 1259.84,772.64 1259.84,885.83 ; v1(1259.84,1008.86) 1259.84,885.83 ; v1(1407.48,885.83) 1259.84,885.83
  Bottom Layer w7.87: U6.36@681.1,1377.95 v2(748.03,1377.95) ; U6.41@681.1,1456.69 723.43,1456.69 v2(748.03,1432.09) ; U6.49@681.1,1582.68 v2(750,1582.68) ; U6.56@681.1,1692.91 v2(748.03,1692.91) ; U6.60@681.1,1755.91 v2(747.05,1755.91) ; U6.24@866.14,1271.65 v2(866.14,1338.58) ; v2(866.14,1811.02) U6.73@866.14,1877.95 ; U6.17@976.38,1271.65 U6.16@992.13,1271.65 992.13,1311.02 984.25,1318.9 v2(984.25,1338.58) ; U6.80@976.38,1877.95 U6.81@992.13,1877.95 992.13,1838.58 984.25,1830.71 v2(984.25,1811.02) ; U6.11@1070.87,1271.65 1070.87,1312.01 1077.76,1318.9 v2(1077.76,1338.58) ; v2(1086.61,1812.01) U6.87@1086.61,1877.95 ; v2(1220.47,1456.69) U6.120@1287.4,1456.69 ; v2(1221.46,1362.2) U6.126@1287.4,1362.2 ; v2(1222.44,1740.16) U6.102@1287.4,1740.16 U6.101@1287.4,1755.91
  Bottom Layer w9.84: v2(187.01,816.93) R54.1@223.23,816.93 v2(187.01,816.93)
  Bottom Layer w19.68: v1(1407.48,885.83) R34.2@1448.82,885.83
  other v1: 1235.24,1023.62 1259.84,1033.46 1235.24,1048.23 1259.84,1058.07
1.8V: C63.2 C91.2 C92.2 J26.1 U5.5 U8.3 U9.8 | length 995.8
  Copper Layer 3 w19.68: v2(1476.38,1336.61) 1730.31,1336.61 1756.89,1363.19 1771.65,1377.95 1771.65,1425.59 ; v1(1574.8,1614.17) 1574.8,1594.49 v1(1653.54,1515.75) 1653.54,1476.38 1704.33,1425.59 1771.65,1425.59 ; J26.1@1870.08,1425.59 1771.65,1425.59
  Bottom Layer w7.87: C91.2@1474.41,1370.08 U9.8@1474.41,1403.54
  Bottom Layer w9.84: C91.2@1474.41,1370.08 1476.38,1368.11 C91.2@1476.38,1366.14 ; U8.3@1647.64,1440.94 1647.64,1485.24 C92.2@1653.54,1491.14 v1(1653.54,1515.75)
  Bottom Layer w19.68: v2(1476.38,1336.61) C91.2@1476.38,1366.14 ; v1(1574.8,1614.17) C63.2@1604.33,1614.17 1650.59,1614.17 U5.5@1655.51,1619.09
3.3V: C43.1 C44.2 C45.2 C46.2 C47.2 C48.2 C49.2 C50.2 C51.2 C52.2 C53.2 C54.2 C55.2 C56.2 C57.2 C58.1 C62.1 C81.2 C85.2 C86.2 C88.2 C89.2 C90.2 C93.1 C94.1 C95.1 C96.1 C97.1 C100.1 C101.1 C104.1 C114.1 C115.1 C116.1 C117.1 J26.3 R32.2 R33.1 R36.1 R37.1 R38.1 R41.2 R45.2 R50.1 R51.1 R55.1 R57.1 R66.2 S2.6 U3.5 U3.6 U4.1 U4.4 U5.1 U5.3 U6.6 U6.14 U6.19 U6.29 U6.42 U6.44 U6.52 U6.67 U6.78 U6.83 U6.92 U6.105 U6.110 U6.111 U7.7 U8.6 U8.7 U9.1 U10.5 U11.1 U11.6 U12.2 U13.5 U13.14 U13.15 U13.16 U14.1 U15.22 U15.36 U15.42 U16.8 U17.8 U18.5 U19.8 Y1.4 | length 11797.5
  Top Layer w7.87: C49.2@713.58,1471.46 714.57,1472.44 v2(747.05,1472.44) ; C48.2@713.58,1505.91 715.55,1503.94 v2(750,1503.94) ; C50.2@713.58,1628.94 714.57,1629.92 v2(747.05,1629.92) ; v2(771.65,1812.01) 771.65,1844.49 C51.2@772.64,1845.47 ; C47.2@787.4,1304.13 v2(787.4,1338.58) ; v1(895.86,944.88) 933.07,944.88 R45.2@935.04,942.91 ; C46.2@944.88,1304.13 v2(944.88,1338.58) ; v2(944.88,1811.02) C52.2@944.88,1845.47 ; C45.2@1023.62,1304.13 v2(1023.62,1338.58) ; v2(1023.62,1811.02) C53.2@1023.62,1845.47 ; C44.2@1146.65,1304.13 1149.61,1307.09 v2(1149.61,1336.61) ; v2(1165.35,1812.01) 1165.35,1844.49 C54.2@1166.34,1845.47 ; v2(1220.47,1614.17) C56.2@1254.92,1614.17 ; v1(1294.29,2386.81) 1305.12,2397.64 U13.5@1305.12,2413.39 ; v1(1309.06,2568.9) C95.1@1309.06,2539.37 1305.12,2535.43 U13.16@1305.12,2507.87 U13.15@1320.87,2507.87 U13.14@1336.61,2507.87
  Top Layer w9.84: R32.2@359.25,2079.72 v1@402.11,2122.58 ; v2(393.7,600.39) R50.1@393.7,646.46 ; v2(467.52,2785.43) U15.22@522.64,2785.43 ; R66.2@757.87,2593.5 794.29,2593.5 C96.1@797.24,2596.46 ; v2(797.24,2554.13) C96.1@797.24,2596.46 ; U15.36@797.24,2687.99 C97.1@797.24,2637.8 799.21,2635.83 C96.1@799.21,2598.43 C96.1@797.24,2596.46 ; v1(797.24,2854.33) 807.09,2844.49 U15.42@855.32,2844.49 ; v1(949.8,3159.45) 1009.65,3099.61 S2.6@1081.1,3099.61 ; v2(1220.47,1678.15) C55.2@1254.92,1678.15
  Copper Layer 3 w7.87: v1(1294.29,2386.81) 1294.29,2519.68 1309.06,2534.45 v1(1309.06,2568.9)
  Copper Layer 3 w9.84: v2(1437.01,1336.61) 1437.01,1284.45 1461.61,1259.84 v1(1500.98,1259.84)
  Copper Layer 3 w19.68: U14.1@282.28,2462.2 282.28,2656.02 344.49,2718.22 344.49,2790.16 ; v2(285.43,698.82) 285.43,634.84 319.88,600.39 v2(393.7,600.39) 442.91,649.61 442.91,738.19 v2(492.13,787.4) v2(492.13,836.61) 600.39,944.88 v1(895.86,944.88) 944.88,993.9 v2(944.88,1338.58) ; v2(467.52,2785.43) 349.21,2785.43 344.49,2790.16 ; 620.08,2047.24 v2(688.98,2047.24) 767.72,2047.24 821.85,1993.11 885.83,1993.11 ; v2(787.4,1161.42) v2(787.4,1338.58) ; 866.14,3021.65 856.3,3031.5 v2(374.02,3031.5) 374.02,2948.03 280.32,2854.33 344.49,2790.16 ; v2(885.83,2047.24) 885.83,1993.11 ; 1082.68,1998.03 v2(1082.68,2047.24) ; v2@1151.57,1338.58 1151.57,1387.8 1176.18,1412.4 1392.72,1412.4 1437.01,1368.11 1437.01,1338.58 v2(1437.01,1336.61) ; v2(1220.47,1614.17) 1387.8,1614.17 1418.34,1644.71 1642.69,1644.71 1732.28,1555.12 v1(1732.28,1515.75) ; 1240.16,1486.22 1471.46,1486.22 v2(1491.14,1505.91) ; v2(1279.53,2047.24) 1225.39,1993.11 885.83,1993.11 ; v1(1422.24,920.28) 1461.61,920.28 ; v1(1555.12,1053.15) 1500.98,999.02 1500.98,959.65 1461.61,920.28 ; v1(1584.65,1053.15) 1584.65,1008.86 1633.86,959.65 v1(1904.53,959.65) ; v1(1624.02,720.55) 1624.02,760.08 1602.38,781.72 1538.48,781.72 1461.61,858.58 1461.61,920.28 ; v2(1653.54,1840.55) 1653.54,1786.42 1712.6,1727.36 v2(1771.65,1727.36)
  Copper Layer 3 w29.53: 905.51,2637.8 974.41,2568.9 v1(1309.06,2568.9) ; v2(1149.61,1336.61) 1149.61,1271.65 1240.16,1181.1 1505.91,1181.1 1555.12,1131.89 v1(1555.12,1053.15) ; 1199.7,1781.5 1258.75,1840.55 v2(1653.54,1840.55) 1766.85,1840.55 1870.08,1737.32 J26.3@1870.08,1625.59
  Bottom Layer w5.91: U10.5@456.3,787.4 U10.5@458.66,787.4 v2(492.13,787.4)
  Bottom Layer w7.87: v2(285.43,698.82) 285.43,738.19 284.45,739.17 U11.1@284.45,767.72 U11.6@307.09,767.72 ; R55.1@455.91,836.61 v2(492.13,836.61) ; R41.2@605.32,1653.54 625,1653.54 648.62,1629.92 U6.52@681.1,1629.92 v2(747.05,1629.92) ; U6.42@681.1,1472.44 v2(747.05,1472.44) ; U6.44@681.1,1503.94 v2(750,1503.94) ; v2(771.65,1812.01) U6.67@771.65,1877.95 ; v2(787.4,1161.42) 816.93,1161.42 R36.1@821.85,1166.34 ; U6.29@787.4,1271.65 v2(787.4,1338.58) ; U6.19@944.88,1271.65 v2(944.88,1338.58) ; v2(944.88,1811.02) U6.78@944.88,1877.95 ; U6.14@1023.62,1271.65 v2(1023.62,1338.58) ; v2(1023.62,1811.02) U6.83@1023.62,1877.95 ; U6.6@1149.61,1271.65 v2(1149.61,1336.61) ; v2(1165.35,1812.01) U6.92@1165.35,1877.95 ; v2(1220.47,1614.17) U6.110@1287.4,1614.17 U6.111@1287.4,1598.43 ; v2(1220.47,1678.15) 1235.24,1692.91 U6.105@1287.4,1692.91 ; Y1.4@1395,1300 1403.88,1303.33 C85.2@1442.91,1303.15 ; C89.2@1437.01,1368.11 1438.98,1370.08 U9.1@1438.98,1403.54
  Bottom Layer w9.84: U14.1@282.28,2462.2 342.91,2462.2 C93.1@344.49,2460.63 ; v2(374.02,3031.5) C104.1@408.46,3031.5 409.45,3032.48 U18.5@447.83,3032.48 ; C81.2@467.52,2746.06 v2(467.52,2785.43) ; v2(492.13,787.4) C117.1@526.57,787.4 ; v2(688.98,2047.24) C115.1@728.35,2047.24 728.35,2052.17 747.84,2071.66 747.84,2086.42 U19.8@749.02,2087.6 ; C101.1@728.35,2852.36 765.75,2852.36 C100.1@767.72,2854.33 v1(797.24,2854.33) ; v2(885.83,2047.24) C116.1@925.2,2047.24 925.2,2052.17 944.69,2071.66 944.69,2086.42 U16.8@945.87,2087.6 ; v2(1082.68,2047.24) C88.2@1122.05,2047.24 1122.05,2052.17 1141.54,2071.66 1141.54,2086.42 U17.8@1142.72,2087.6 ; v2(1279.53,2047.24) C114.1@1318.9,2047.24 C114.1@1318.9,2052.17 ; v1(1422.24,920.28) U4.1@1422.24,944.88 ; C89.2@1437.01,1368.11 v2(1437.01,1336.61) 1437.01,1318.9 1446.85,1309.06 C85.2@1446.85,1304.13 C85.2@1446.85,1299.21 ; R51.1@1459.84,1505.91 v2(1491.14,1505.91) ; R57.1@1474.61,1259.84 v1(1500.98,1259.84) ; R38.1@1584.65,720.55 v1(1624.02,720.55) R37.1@1663.39,720.55 ; v1(1732.28,1515.75) C90.2@1732.28,1491.14 1724.41,1483.27 U8.6@1724.41,1440.94 U8.7@1750,1440.94 ; U7.7@1834.65,974.41 1860.24,974.41 C57.2@1875,959.65
  Bottom Layer w10: Y1.4@1393.54,1299.21 1394.33,1300 Y1.4@1395,1300
  Bottom Layer w19.68: U12.2@280.32,2854.33 C94.1@344.49,2854.33 ; v2(1653.54,1840.55) 1653.54,1793.31 1655.51,1791.34 U5.1@1655.51,1727.36 ; U5.3@1732.28,1727.36 v2(1771.65,1727.36) ; C57.2@1875,959.65 v1(1904.53,959.65)
  other v1: 497.05,2091.54 497.05,2116.14 403.54,2124.14 497.05,2140.75 403.54,2148.75 442.91,2170.28 920.28,3159.45 935.04,3179.13
3.3V-TP: J21.1 R33.2
5V-SPDIF: C98.1 C99.1 L7.2 R31.1 U15.46 | length 1993
  Top Layer w9.84: v1(797.24,2937.99) 812.01,2923.23 U15.46@855.32,2923.23
  Top Layer w19.68: v1(285.43,1702.76) 343.5,1702.76 L7.2@344.49,1703.74
  Top Layer w40: v1(298.87,1763.13) R31.1@343.16,1763.13
  Copper Layer 3 w19.68: v1(285.43,1702.76) 285.43,1749.7 v1(298.87,1763.13) 221.87,1763.13 110,1875 110,2137.5 147.5,2175 314.76,2175 393.7,2253.94 393.7,2506.97 430.22,2543.48 430.22,2570.96 v1(797.24,2937.99)
  Bottom Layer w9.84: C98.1@728.35,2960.63 736.22,2952.76 752.95,2952.76 757.87,2947.83 C99.1@767.72,2937.99 v1(797.24,2937.99)
5V-U3: C42.2 J19.1 R31.2 U3.3 U3.4
  other v1: 245,1837.5 196.85,1887.5 196.85,1952.5 191.93,2091.54 280.51,2091.54 206.69,2116.14 265.75,2116.14 191.93,2140.75 280.51,2140.75
9211-LOCK: U15.1 U18.2 | length 333
  Top Layer w9.84: v2(777.56,3075.79) 797.24,3056.1 U15.1@797.24,3020.67
  Bottom Layer w9.84: U18.2@536.42,3006.89 570.87,3006.89 639.76,3075.79 v2(777.56,3075.79)
\PDN: C22.1 J9.1 R5.1 R7.1 R80.2 S1.5 TP4.1 U1.4 | length 4795.5
  Top Layer w9.84: U1.4@3153.72,1855.29 v1(3199.11,1855.29)
  Top Layer w10: S1.5@2386.29,426.08 2534.92,426.08 R7.1@2535.5,425.5 2541.18,431.18 v1@2603.5,431.18
  Bottom Layer w9.84: R80.2@1553.15,2864.17 v1(1594.49,2864.17) ; v1(2602.5,430) 2657.5,485 2715,485 2820.55,590.55 3005.55,590.55 3092.5,677.5 3092.5,772.82 3148.5,828.82 3148.5,1408.65 3331.72,1591.87 3331.72,1724.23 3229.82,1826.14 R5.1@3229.82,1855.29 v1(3199.11,1855.29)
  Bottom Layer w10: v1(1594.49,2864.17) 2150.72,2864.17 2208.28,2806.61 2208.28,2365.34 2164.2,2321.26 TP4.1@2164.2,2211.5 2164.2,2044.14 J9.1@2156.62,2036.56 2173.18,2020 3011.62,2020 3176.34,1855.29 v1(3199.11,1855.29)
\TRST: R48.1 U6.123 | length 144.1
  Bottom Layer w7.87: U6.123@1287.4,1409.45 1340.55,1409.45 1363.19,1432.09 1363.19,1457.87 R48.1@1386.61,1481.3
ADR: J8.2 U1.13 | length 1153.8
  Top Layer w10: J8.2@2082.31,1499.37 2229.17,1499.37 2384.8,1655 3060,1655 3090.03,1624.97 U1.13@3153.72,1624.97 U1.13@3149.86,1628.83
AMP_SCL: J11.2 J22.1 TP19.1 U1.5 | length 3194.2
  Top Layer w10: TP19.1@1413,550 J22.1@1413,372 1761.45,372 2190,800.55 2190,895.35 J11.2@2127.41,957.95 ; v1(3092.5,1829.69) U1.5@3153.72,1829.69
  Bottom Layer w9.84: J11.2@2127.41,957.95 2118.78,957.95 2058.79,1017.93 2058.79,1117.58 1952.65,1223.72 1952.65,1307.93 1970.96,1326.24 2143.14,1326.24 2550.8,1733.9 3054.28,1733.9 3092.5,1772.12 v1(3092.5,1829.69)
AMP_SDA: J10.2 J23.1 TP20.1 U1.6 | length 3042.1
  Top Layer w9.84: TP20.1@1195,545 1250,545 1490,785 1695,785 1720,810 1720,895 1756.42,931.42 1951.38,931.42 1980.41,960.45 J10.2@1980.41,960.95 ; v1(3061.88,1804.1) U1.6@3153.72,1804.1
  Top Layer w10: J23.1@1195,375 TP20.1@1195,545
  Bottom Layer w9.84: J10.2@1980.41,960.95 2036.01,1016.55 2036.01,1103.08 1932.55,1206.54 1932.55,1318.56 1961.68,1347.7 2132.82,1347.7 2545.12,1760 3048.6,1760 3062.5,1773.9 3062.5,1803.48 v1(3061.88,1804.1)
BCLK-XMOS: R43.2 R52.2 U16.2 | length 2406.7
  Top Layer w9.84: v2(537.5,1917.5) 613.11,1993.11 v2(757.87,1993.11) 757.87,2137.75 815,2194.88 v2(989.17,2194.88)
  Bottom Layer w7.87: v2@537.5,1915 537.5,1669.39 450.63,1582.52 450.63,1074.96 738.19,787.4 R52.2@1120.87,787.4
  Bottom Layer w9.84: R43.2@757.87,1958.66 v2(757.87,1993.11) ; U16.2@971.46,2243.11 971.46,2212.6 v2(989.17,2194.88)
BIAS: C33.2 C34.1 L5.1 R12.2 R13.2 R16.1 U2.1 U2.2 | length 1810.7
  Top Layer w9.84: L5.1@2040.17,3875.65 v1(2040.17,3904.59) ; v1(2500.17,4605.65) R13.2@2536.67,4605.65 2536.67,4661.71 R16.1@2540.6,4665.65
  Copper Layer 3 w9.84: 2419.67,4525.15 v1(2500.17,4605.65)
  Copper Layer 3 w10: v1(2040.17,3904.59) 2040.17,4044.65 2296.17,4300.65 2296.17,4401.65 2419.67,4525.15
  Copper Layer 3 w50: 2017.17,3824.65 2110.17,3824.65 2329.17,4043.65 2329.17,4213.65 2419.17,4303.65 2511.17,4303.65
  other v1: 1700.17,3770.65 1725.17,3770.65 1750.17,3770.65 1775.17,3770.65 1800.17,3770.65 1825.17,3770.65 1850.17,3770.65 1875.17,3770.65 1900.17,3770.65 1925.17,3770.65 1950.17,3770.65 1975.17,3770.65 2520.17,4280.65 2547.67,4280.65 2575.17,4280.65
BST_A+: C14.1 TP21.1 U1.20 | length 889.5
  Top Layer w9.84: U1.20@3449,1624.97 3537.89,1624.97 v1(3603.86,1559) C14.1@3651.25,1559
  Bottom Layer w10: v1(3603.86,1559) 3605.14,1560.28 4260.75,1560.28 TP21.1@4262.5,1558.52
BST_A-: C16.1 TP22.1 U1.24 | length 881.3
  Top Layer w9.84: 3621.5,1710.36 C16.1@3651.28,1710.36
  Top Layer w10: U1.24@3449,1727.33 3595.17,1727.33 v1(3600,1722.5) 3609.36,1722.5 3621.5,1710.36
  Bottom Layer w10: v1@3600,1722.36 3609.5,1722.36 3635.89,1695.97 4257.56,1695.97 TP22.1@4260,1693.52
BST_B+: C18.1 TP23.1 U1.29 | length 897.2
  Top Layer w9.84: U1.29@3449,1855.29 3537.89,1855.29 v1(3603.61,1921) C18.1@3650,1921
  Bottom Layer w10: v1(3603.61,1921) 3645.97,1963.37 TP23.1@4255,1963.37
BST_B-: C20.1 TP24.1 U1.25 | length 897.7
  Top Layer w10: U1.25@3449,1752.92 3590.42,1752.92 v1(3600,1762.5) 3607.4,1769.9 C20.1@3651.28,1769.9
  Bottom Layer w10: v1(3600,1762.5) 3668.52,1831.02 TP24.1@4260,1831.02
COMP: C38.1 C39.1 U2.6 | length 150.1
  Top Layer w9.84: U2.6@2717.77,4335.49 2717.77,4324.13 2745.78,4296.12 2756.76,4296.12 2781.75,4271.14 C38.1@2781.75,4266.6 C39.1@2829.97,4266.6
CS: R17.1 U2.5 | length 82.2
  Top Layer w9.84: U2.5@2698.08,4335.49 2698.08,4318.76 2722.69,4294.16 2722.69,4277.42 R17.1@2732.53,4267.58
DOUT-XMOS: R47.2 U19.2 | length 2100
  Top Layer w9.84: v2(426,1154) 497.32,1082.68 935.04,1082.68 1043.31,1190.94 v1(1131.89,1190.94) ; v1(490,1917.5) 489.11,1918.39 489.11,1990.09 v2(693.9,2194.88)
  Bottom Layer w9.84: v2(426,1154) 426,1591 490,1655 v1(490,1917.5) ; v2(693.9,2194.88) 757.87,2194.88 774.61,2211.61 U19.2@774.61,2243.11 ; v1(1131.89,1190.94) R47.2@1179.92,1190.94
DVDD1: C11.2 C12.1 J3.2 R1.2 R2.2 R3.2 R4.2 R5.2 R7.2 R8.2 R9.2 U1.15 | length 4439.1
  Top Layer w10: C12.1@2923.28,1535 2980.17,1535 3018.96,1573.79 U1.15@3153.72,1573.79
  Top Layer w20: R8.2@1757.98,1099.99 R9.2@1812.49,1099.99 1811.65,1100.82 1811.65,1146.65 1852.99,1187.99 2078.68,1187.99 2102.69,1212 J3.2@2102.69,1267.97 ; R1.2@2233.15,1347.44 2233.15,1304.15 2225,1296 ; R7.2@2535,465.37 R7.2@2535.5,464.87 2535.5,568 2229.57,873.93 2229.57,1156.43 2118.03,1267.97 J3.2@2102.69,1267.97 ; C11.2@2923.28,1475 C12.1@2923.28,1535 ; C11.2@2926.62,1463.69 2758.93,1296 2225,1296 ; J3.2@2102.69,1267.97 2130.72,1296 v1(2167,1296) v1(2197,1296) 2225,1296
  Copper Layer 3 w20: J3.2@2102.69,1267.97 2130.87,1296.15 v1@2197,1296.15 ; v1(2197,1296) 2211,1310 2455,1310.22 2760,1310.22 3014.7,1564.92 3252.61,1564.92 3301.89,1614.2 v1(3301.89,1637.15) v1(3301.89,1676.15) v1(3301.89,1715.15) v1@3301.89,1853.29
  Copper Layer 3 w25: v1@3299.64,1855.04 v1(3299.89,1855.29) v1@3300.14,1855.54
  Bottom Layer w9.84: R2.2@3271.19,1637.15 v1(3301.89,1637.15) ; R3.2@3271.19,1676.15 v1(3301.89,1676.15) ; R4.2@3271.19,1715.15 v1(3301.89,1715.15)
  Bottom Layer w10: R5.2@3269.19,1855.29 v1(3299.89,1855.29)
FB: R25.1 U2.8 | length 279.3
  Top Layer w9.84: U2.8@2698.08,4410.3 2698.08,4441.79
  Top Layer w10: 2698.08,4441.79 2706.29,4450 R25.1@2942.44,4450
GATE: R15.1 U2.3 | length 68.3
  Top Layer w9.84: R15.1@2629.19,4279.39 2639.03,4289.23 2639.03,4299.08 2658.71,4318.76 U2.3@2658.71,4335.49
